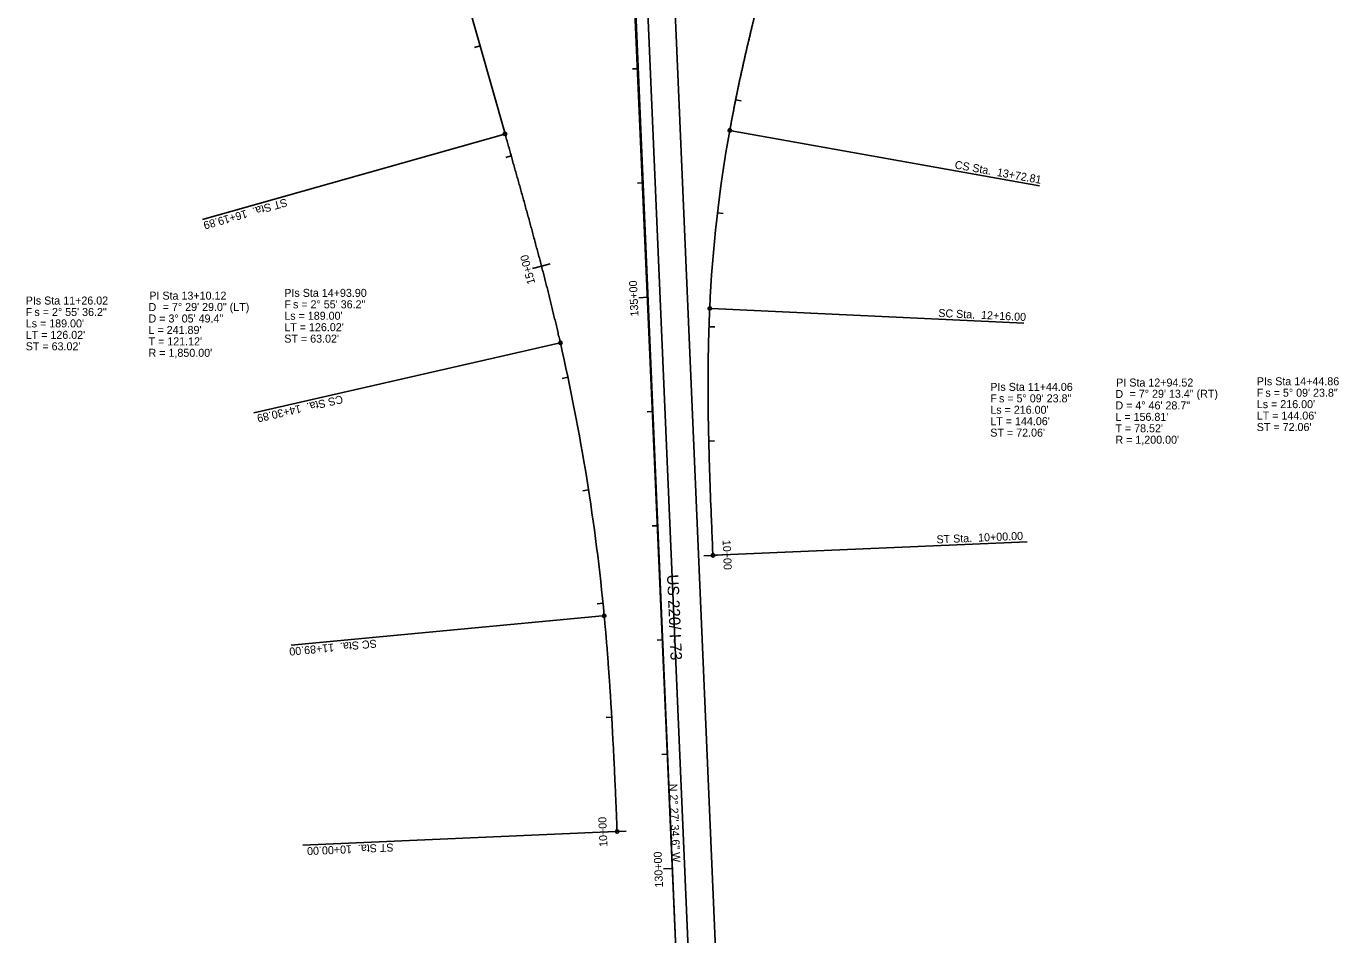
# Model space of a CAD drawing. Extents: x 1722038 to 1726172, y 967033 to 975427.
# Drawn here: x 1723434 to 1724581, y 970348 to 971142 of the extents above; entities that cross this region are included whole.
import ezdxf

# ---------------------------------------------------------------- set-up
doc = ezdxf.new("R2010")
doc.units = 0
for name, color, linetype in [('Prop Horizontal Alignment', 7, 'Continuous'), ('Prop Horizontal Alignment Curve and Spiral Data', 7, 'Continuous'), ('Prop Horizontal Alignment Direction Label', 7, 'Continuous'), ('Prop Horizontal Alignment Station Label', 7, 'Continuous'), ('Prop Horizontal Alignment Tick Label', 7, 'Continuous'), ('Prop Horizontal Alignment Tick Large', 7, 'Continuous'), ('Prop Horizontal Alignment Tick Small', 7, 'Continuous')]:
    doc.layers.add(name, color=color, linetype=linetype)

msp = doc.modelspace()

# ---------------------------------------------------------------- linework, layer by layer
at = {"layer": 'Prop Horizontal Alignment'}
for p, q in [((1724069.6, 968773.8), (1723927.1, 972039.3)), ((1724065.2, 968856.7), (1723928.8, 972032.2)), ((1724075.7, 968857.1), (1723939.3, 972032.7)), ((1724099.7, 968858.1), (1723963.3, 972033.7)), ((1723852.2, 971048.3), (1723641.8, 971791.5))]:
    msp.add_line(p, q, dxfattribs=at)
for centre, radius, start, end in [((1725229.8, 970839.2), 1200, 169.816, 177.303), ((1722097.1, 970453.3), 1850, 5.3863, 12.8777)]:
    msp.add_arc(centre, radius, start, end, dxfattribs=at)
for points in [[(1724099.6, 971261.3), (1724098.8, 971258.4), (1724098.1, 971255.6), (1724097.3, 971252.8), (1724096.5, 971250), (1724095.7, 971247.2), (1724095, 971244.4), (1724094.2, 971241.5), (1724093.4, 971238.7), (1724092.7, 971235.9), (1724091.9, 971233.1), (1724091.1, 971230.3), (1724090.4, 971227.5), (1724089.6, 971224.6), (1724088.8, 971221.8), (1724088.1, 971219), (1724087.3, 971216.2), (1724086.6, 971213.4), (1724085.8, 971210.6), (1724085, 971207.7), (1724084.3, 971204.9), (1724083.5, 971202.1), (1724082.8, 971199.3), (1724082, 971196.5), (1724081.3, 971193.6), (1724080.5, 971190.8), (1724079.8, 971188), (1724079.1, 971185.2), (1724078.3, 971182.3), (1724077.6, 971179.5), (1724076.9, 971176.7), (1724076.1, 971173.9), (1724075.4, 971171), (1724074.7, 971168.2), (1724074, 971165.4), (1724073.2, 971162.6), (1724072.5, 971159.7), (1724071.8, 971156.9), (1724071.1, 971154.1), (1724070.4, 971151.2), (1724069.7, 971148.4), (1724069, 971145.6), (1724068.3, 971142.7), (1724067.6, 971139.9), (1724066.9, 971137), (1724066.3, 971134.2), (1724065.6, 971131.4), (1724064.9, 971128.5), (1724064.2, 971125.7), (1724063.6, 971122.8), (1724062.9, 971120), (1724062.3, 971117.2), (1724061.6, 971114.3), (1724061, 971111.5), (1724060.3, 971108.6), (1724059.7, 971105.8), (1724059.1, 971102.9), (1724058.5, 971100.1), (1724057.8, 971097.2), (1724057.2, 971094.4), (1724056.6, 971091.5), (1724056, 971088.6), (1724055.4, 971085.8), (1724054.8, 971082.9), (1724054.2, 971080.1), (1724053.7, 971077.2), (1724053.1, 971074.3), (1724052.5, 971071.5), (1724052, 971068.6), (1724051.4, 971065.8), (1724050.9, 971062.9), (1724050.3, 971060), (1724049.8, 971057.1), (1724049.3, 971054.3), (1724048.8, 971051.4)], [(1723852.2, 971048.3), (1723852.9, 971045.9), (1723853.6, 971043.4), (1723854.3, 971040.9), (1723855, 971038.5), (1723855.7, 971036), (1723856.4, 971033.6), (1723857.1, 971031.1), (1723857.8, 971028.6), (1723858.5, 971026.2), (1723859.1, 971023.7), (1723859.8, 971021.3), (1723860.5, 971018.8), (1723861.2, 971016.4), (1723861.9, 971013.9), (1723862.6, 971011.4), (1723863.3, 971009), (1723864, 971006.5), (1723864.7, 971004.1), (1723865.4, 971001.6), (1723866.1, 970999.1), (1723866.7, 970996.7), (1723867.4, 970994.2), (1723868.1, 970991.8), (1723868.8, 970989.3), (1723869.5, 970986.8), (1723870.2, 970984.4), (1723870.8, 970981.9), (1723871.5, 970979.5), (1723872.2, 970977), (1723872.9, 970974.5), (1723873.5, 970972.1), (1723874.2, 970969.6), (1723874.9, 970967.1), (1723875.5, 970964.7), (1723876.2, 970962.2), (1723876.9, 970959.7), (1723877.5, 970957.3), (1723878.2, 970954.8), (1723878.9, 970952.3), (1723879.5, 970949.9), (1723880.2, 970947.4), (1723880.8, 970944.9), (1723881.5, 970942.5), (1723882.2, 970940), (1723882.8, 970937.5), (1723883.5, 970935.1), (1723884.1, 970932.6), (1723884.7, 970930.1), (1723885.4, 970927.6), (1723886, 970925.2), (1723886.7, 970922.7), (1723887.3, 970920.2), (1723887.9, 970917.8), (1723888.6, 970915.3), (1723889.2, 970912.8), (1723889.8, 970910.3), (1723890.4, 970907.8), (1723891, 970905.4), (1723891.7, 970902.9), (1723892.3, 970900.4), (1723892.9, 970897.9), (1723893.5, 970895.5), (1723894.1, 970893), (1723894.7, 970890.5), (1723895.3, 970888), (1723895.9, 970885.5), (1723896.5, 970883), (1723897.1, 970880.6), (1723897.7, 970878.1), (1723898.3, 970875.6), (1723898.8, 970873.1), (1723899.4, 970870.6), (1723900, 970868.1), (1723900.6, 970865.6)], [(1724034, 970679.8), (1724033.8, 970682.7), (1724033.7, 970685.6), (1724033.6, 970688.5), (1724033.5, 970691.5), (1724033.3, 970694.4), (1724033.2, 970697.3), (1724033.1, 970700.2), (1724033, 970703.1), (1724032.9, 970706), (1724032.7, 970709), (1724032.6, 970711.9), (1724032.5, 970714.8), (1724032.4, 970717.7), (1724032.3, 970720.6), (1724032.1, 970723.5), (1724032, 970726.5), (1724031.9, 970729.4), (1724031.8, 970732.3), (1724031.7, 970735.2), (1724031.6, 970738.1), (1724031.5, 970741), (1724031.4, 970744), (1724031.3, 970746.9), (1724031.2, 970749.8), (1724031.1, 970752.7), (1724031, 970755.6), (1724030.9, 970758.5), (1724030.8, 970761.5), (1724030.7, 970764.4), (1724030.6, 970767.3), (1724030.6, 970770.2), (1724030.5, 970773.1), (1724030.4, 970776), (1724030.3, 970779), (1724030.3, 970781.9), (1724030.2, 970784.8), (1724030.1, 970787.7), (1724030.1, 970790.6), (1724030, 970793.6), (1724030, 970796.5), (1724029.9, 970799.4), (1724029.9, 970802.3), (1724029.9, 970805.2), (1724029.8, 970808.2), (1724029.8, 970811.1), (1724029.8, 970814), (1724029.7, 970816.9), (1724029.7, 970819.8), (1724029.7, 970822.7), (1724029.7, 970825.7), (1724029.7, 970828.6), (1724029.7, 970831.5), (1724029.7, 970834.4), (1724029.7, 970837.3), (1724029.7, 970840.3), (1724029.8, 970843.2), (1724029.8, 970846.1), (1724029.8, 970849), (1724029.9, 970851.9), (1724029.9, 970854.9), (1724030, 970857.8), (1724030, 970860.7), (1724030.1, 970863.6), (1724030.1, 970866.5), (1724030.2, 970869.4), (1724030.3, 970872.4), (1724030.4, 970875.3), (1724030.5, 970878.2), (1724030.6, 970881.1), (1724030.7, 970884), (1724030.8, 970886.9), (1724030.9, 970889.9), (1724031, 970892.8), (1724031.2, 970895.7)], [(1723950.3, 970438.3), (1723950.1, 970440.9), (1723950, 970443.4), (1723949.9, 970446), (1723949.8, 970448.5), (1723949.7, 970451.1), (1723949.6, 970453.6), (1723949.5, 970456.2), (1723949.4, 970458.8), (1723949.3, 970461.3), (1723949.1, 970463.9), (1723949, 970466.4), (1723948.9, 970469), (1723948.8, 970471.5), (1723948.7, 970474.1), (1723948.6, 970476.6), (1723948.5, 970479.2), (1723948.3, 970481.7), (1723948.2, 970484.3), (1723948.1, 970486.8), (1723948, 970489.4), (1723947.9, 970491.9), (1723947.8, 970494.5), (1723947.6, 970497), (1723947.5, 970499.6), (1723947.4, 970502.1), (1723947.3, 970504.7), (1723947.1, 970507.2), (1723947, 970509.8), (1723946.9, 970512.3), (1723946.7, 970514.9), (1723946.6, 970517.4), (1723946.5, 970520), (1723946.3, 970522.5), (1723946.2, 970525.1), (1723946.1, 970527.6), (1723945.9, 970530.2), (1723945.8, 970532.7), (1723945.7, 970535.3), (1723945.5, 970537.8), (1723945.4, 970540.4), (1723945.2, 970542.9), (1723945.1, 970545.5), (1723944.9, 970548), (1723944.8, 970550.6), (1723944.6, 970553.1), (1723944.4, 970555.7), (1723944.3, 970558.2), (1723944.1, 970560.8), (1723943.9, 970563.3), (1723943.8, 970565.9), (1723943.6, 970568.4), (1723943.4, 970571), (1723943.3, 970573.5), (1723943.1, 970576.1), (1723942.9, 970578.6), (1723942.7, 970581.2), (1723942.5, 970583.7), (1723942.3, 970586.3), (1723942.2, 970588.8), (1723942, 970591.3), (1723941.8, 970593.9), (1723941.6, 970596.4), (1723941.4, 970599), (1723941.2, 970601.5), (1723940.9, 970604.1), (1723940.7, 970606.6), (1723940.5, 970609.2), (1723940.3, 970611.7), (1723940.1, 970614.3), (1723939.9, 970616.8), (1723939.6, 970619.3), (1723939.4, 970621.9), (1723939.2, 970624.4), (1723938.9, 970627)]]:
    msp.add_spline(points, degree=3, dxfattribs=at)
at = {"layer": 'Prop Horizontal Alignment Station Label'}
for p, q in [((1723850.8, 971047.9), (1723587.6, 970973.4)), ((1724050.2, 971051.1), (1724319.4, 971002.8)), ((1724032.7, 970895.6), (1724305.9, 970882.8)), ((1723899.1, 970865.3), (1723632.5, 970804.3)), ((1724035.5, 970679.9), (1724308.7, 970691.6)), ((1723937.4, 970626.8), (1723665.1, 970601.2)), ((1723948.8, 970438.3), (1723675.5, 970426.5))]:
    msp.add_line(p, q, dxfattribs=at)
for centre in [(1723852.2, 971048.3), (1724048.8, 971051.4), (1724031.2, 970895.7), (1723900.6, 970865.6), (1724034, 970679.8), (1723938.9, 970627), (1723950.3, 970438.3)]:
    msp.add_circle(centre, 1.5, dxfattribs=at)
at = {"layer": 'Prop Horizontal Alignment Tick Large'}
for p, q in [((1723884.1, 970932.7), (1723876.3, 970930.7)), ((1723884.1, 970932.7), (1723891.8, 970934.8)), ((1723977.2, 970905.5), (1723969.2, 970905.1)), ((1724034, 970679.8), (1724026, 970679.4)), ((1724034, 970679.8), (1724042, 970680.1)), ((1723950.3, 970438.3), (1723942.3, 970438)), ((1723950.3, 970438.3), (1723958.2, 970438.7)), ((1723998.7, 970405.9), (1723990.7, 970405.6))]:
    msp.add_line(p, q, dxfattribs=at)
at = {"layer": 'Prop Horizontal Alignment Tick Small'}
for p, q in [((1723830.4, 971125.4), (1723825.6, 971124)), ((1723968.6, 971105.3), (1723963.6, 971105.1)), ((1724053.8, 971078.1), (1724058.8, 971077.1)), ((1723857.6, 971029.2), (1723852.8, 971027.8)), ((1723972.9, 971005.4), (1723967.9, 971005.2)), ((1724038.1, 970979.4), (1724043, 970978.8)), ((1724030.5, 970879.7), (1724035.5, 970879.5)), ((1723907.2, 970835.5), (1723902.3, 970834.4)), ((1723981.5, 970805.6), (1723976.5, 970805.4)), ((1724030.3, 970779.7), (1724035.3, 970779.8)), ((1723925.2, 970737.1), (1723920.3, 970736.3)), ((1723985.8, 970705.7), (1723980.8, 970705.5)), ((1723937.9, 970637.9), (1723932.9, 970637.4)), ((1723990.1, 970605.8), (1723985.1, 970605.5)), ((1723945.5, 970538.2), (1723940.5, 970537.9)), ((1723994.4, 970505.9), (1723989.4, 970505.6))]:
    msp.add_line(p, q, dxfattribs=at)

# ---------------------------------------------------------------- texts
at = {"layer": 'Prop Horizontal Alignment Curve and Spiral Data'}
for s, p in [('PI Sta 13+10.12', (1723541.2, 970903.4)), ('PIs Sta 14+93.90', (1723659.2, 970905.8)), ('PIs Sta 11+26.02', (1723433.1, 970899.1)), ('F', (1723433.1, 970889.1)), ('s = 2%%d 55\' 36.2"', (1723440.7, 970889.1)), ('D', (1723540.5, 970893.4)), ('= 7%%d 29\' 29.0" (LT)', (1723552.9, 970893.5)), ('F', (1723659.2, 970895.8)), ('s = 2%%d 55\' 36.2"', (1723666.8, 970895.8)), ("Ls = 189.00'", (1723433.1, 970879.1)), ('D = 3%%d 05\' 49.4"', (1723540.5, 970883.4)), ("Ls = 189.00'", (1723659.2, 970885.8)), ("LT = 126.02'", (1723433.1, 970869.1)), ("L = 241.89'", (1723540.5, 970873.4)), ("ST = 63.02'", (1723659.2, 970865.8)), ("LT = 126.02'", (1723659.2, 970875.8)), ("ST = 63.02'", (1723433.1, 970859.1)), ("T = 121.12'", (1723540.5, 970863.4)), ("R = 1,850.00'", (1723540.5, 970853.4)), ('PIs Sta 11+44.06', (1724276.5, 970823.6)), ('PI Sta 12+94.52', (1724386.6, 970827.4)), ('PIs Sta 14+44.86', (1724509.5, 970828.5)), ('F', (1724276.5, 970813.6)), ('s = 5%%d 09\' 23.8"', (1724284.1, 970813.6)), ('D', (1724385.9, 970817.4)), ('D = 4%%d 46\' 28.7"', (1724385.9, 970807.4)), ('= 7%%d 29\' 13.4" (RT)', (1724398.3, 970817.6)), ('F', (1724509.5, 970818.5)), ("Ls = 216.00'", (1724509.5, 970808.5)), ('s = 5%%d 09\' 23.8"', (1724517, 970818.5)), ("Ls = 216.00'", (1724276.5, 970803.6)), ("L = 156.81'", (1724385.9, 970797.4)), ("LT = 144.06'", (1724509.5, 970798.5)), ("LT = 144.06'", (1724276.5, 970793.6)), ("T = 78.52'", (1724385.9, 970787.4)), ("ST = 72.06'", (1724509.5, 970788.5)), ("ST = 72.06'", (1724276.5, 970783.6)), ("R = 1,200.00'", (1724385.9, 970777.4))]:
    msp.add_text(s, height=7, dxfattribs=at).set_placement(p)
at = {"layer": 'Prop Horizontal Alignment Direction Label'}
msp.add_text('N 2%%d 27\' 34.6" W', height=7, rotation=272.4596, dxfattribs=at).set_placement((1723995.7, 970479.9))
at = {"layer": 'Prop Horizontal Alignment Station Label'}
for s, rotation, p in [('CS Sta.  13+72.81', 349.816, (1724245, 971018.2)), ('ST Sta.  16+19.89', 195.8045, (1723660.7, 970992)), ('SC Sta.  12+16.00', 357.303, (1724230.9, 970888.3)), ('CS Sta.  14+30.89', 192.8777, (1723709.6, 970819.9)), ('ST Sta.  10+00.00', 2.4595, (1724229.6, 970690.2)), ('SC Sta.  11+89.00', 185.3863, (1723739.7, 970606.2)), ('ST Sta.  10+00.00', 182.4597, (1723754.6, 970427.9))]:
    msp.add_text(s, height=7, rotation=rotation, dxfattribs=at).set_placement(p)
at = {"layer": 'Prop Horizontal Alignment Tick Label'}
for s, height, rotation, p in [('15+00', 7, 104.6269, (1723878.7, 970917.8)), ('135+00', 7, 92.4596, (1723968.9, 970888.8)), ('10+00', 7, 272.4596, (1724042.4, 970693.2)), ('US 220/ I-73', 10, 272.4596, (1723993.8, 970662.9)), ('10+00', 7, 92.4596, (1723941.8, 970425)), ('130+00', 7, 92.4596, (1723990.4, 970389.4))]:
    msp.add_text(s, height=height, rotation=rotation, dxfattribs=at).set_placement(p)

doc.saveas('drawing.dxf')
